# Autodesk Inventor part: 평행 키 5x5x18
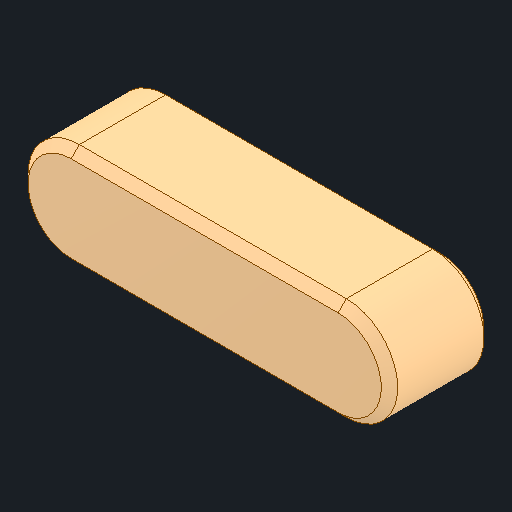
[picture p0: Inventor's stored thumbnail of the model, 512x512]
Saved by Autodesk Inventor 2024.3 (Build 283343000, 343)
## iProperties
Created: 2025-03
Part Number: 평행 키 5x5x18
Material: 강철, 연강
Description: 키 및 해당 키홈
Document SubType Name: Modeling
Designer: user
Density: 7.85 g/cm^3
Appearance: 기본값
Author: jhkim
Sending System: Autodesk Inventor 2025
Preprocessor: ST-DEVELOPER v20
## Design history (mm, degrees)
feature "Solid1"
node "솔리드1"
